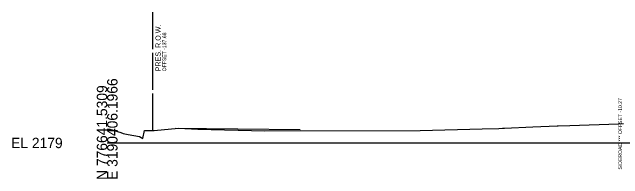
# Model space of a CAD drawing. Extents: x -26 to 303, y -10 to 13517.
# Drawn here: x -25.7 to 139.5, y 8490.3 to 8535.4 of the extents above; entities that cross this region are included whole.
import ezdxf

# ---------------------------------------------------------------- set-up
doc = ezdxf.new("R2010")
doc.units = 0
for name, color, linetype in [('DESIGN - SHEET - Light Grid', 7, 'Continuous'), ('DESIGN - TYPICAL - Finished Grade and Subgrade', 7, 'Continuous'), ('DESIGN - TYPICAL - Text', 7, 'Continuous'), ('SURVEY - GROUND - Top of Ground', 7, 'Continuous'), ('SURVEY - PROPERTY - ROW Lines', 7, 'Continuous'), ('SURVEY - PROPERTY - ROW Lines Text', 7, 'Continuous')]:
    doc.layers.add(name, color=color, linetype=linetype)

msp = doc.modelspace()

# ---------------------------------------------------------------- linework, layer by layer
at = {"layer": 'DESIGN - SHEET - Light Grid'}
msp.add_line((0, 8500), (150, 8500), dxfattribs=at)
at = {"layer": 'DESIGN - TYPICAL - Finished Grade and Subgrade'}
for p, q in [((18.49, 8504.05), (35.35, 8503.8)), ((35.35, 8503.8), (52.23, 8503.61))]:
    msp.add_line(p, q, dxfattribs=at)
at = {"layer": 'SURVEY - GROUND - Top of Ground'}
msp.add_lwpolyline([(0, 8503.73), (0.72, 8503.75), (3.71, 8502.83), (4.3, 8502.57), (5.72, 8502.27), (8.73, 8501.76), (9.64, 8501.23), (10.06, 8503.35), (12.74, 8503.39), (19.32, 8503.99), (24.5, 8503.73), (42.65, 8503.27), (84.72, 8503.38), (101.44, 8503.86), (105.97, 8503.96), (106.99, 8503.98), (107.49, 8504.01), (115.2, 8504.35), (121.72, 8504.61), (122.06, 8504.64), (125.21, 8504.76), (138.36, 8505.2), (139.67, 8505.26)], dxfattribs=at)
at = {"layer": 'SURVEY - PROPERTY - ROW Lines'}
for p, q in [((12.32, 8525.38), (12.32, 8535.38)), ((12.32, 8514.38), (12.32, 8524.38)), ((12.32, 8503.38), (12.32, 8513.38))]:
    msp.add_line(p, q, dxfattribs=at)

# ---------------------------------------------------------------- texts
at = {"layer": 'DESIGN - SHEET - Light Grid'}
for s, p in [('E 3190406.1966', (2.8, 8490)), ('N 776641.5309', (0, 8490))]:
    msp.add_text(s, height=2.8, rotation=90, dxfattribs=at).set_placement(p)
msp.add_text('EL 2179', height=2.8, dxfattribs=at).set_placement((-26, 8498.6))
at = {"layer": 'DESIGN - TYPICAL - Text'}
msp.add_text('SIDEROAD *** OFFSET -10.27', height=1, rotation=90, dxfattribs=at).set_placement((139.29, 8492.8))
at = {"layer": 'SURVEY - PROPERTY - ROW Lines Text'}
for s, height, p in [('PRES. R.O.W.', 1.4, (14.47, 8519.38)), ('OFFSET -137.68', 1, (15.97, 8519.38))]:
    msp.add_text(s, height=height, rotation=90, dxfattribs=at).set_placement(p)

doc.saveas('drawing.dxf')
